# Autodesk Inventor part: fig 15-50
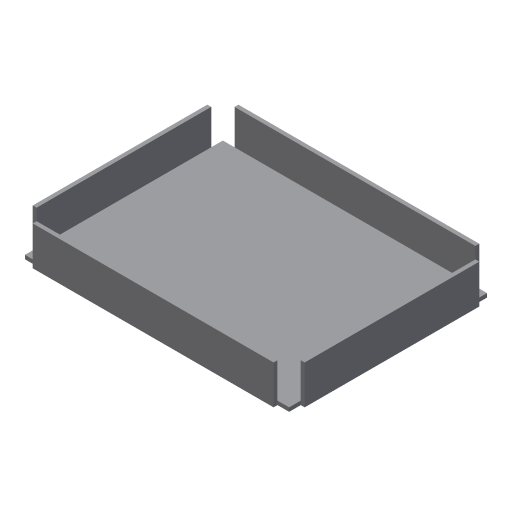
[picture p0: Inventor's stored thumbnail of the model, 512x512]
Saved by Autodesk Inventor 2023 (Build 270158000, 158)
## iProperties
Created: 2002-04
Part Number: fig 15-50
Document SubType Name: Sheet Metal
Density: 1 g/cm^3
Sheet Metal Rule: Default
Material: Generic
Appearance: Default
Control State: 0
Master: False
Checked Out: False
Shininess: 77.0
Angle Display Precision: 2
Document Length Units: 11269
Document Angle Units: 11279
Document Time Units: 11290
Document Mass Units: 11283
Document Length Units Precision: 3
Document Angle Units Precision: 2
Compacted: True
Density: 0.0
Volumn: 0.0
Area: 0.0
PropertySet Name: Model Information
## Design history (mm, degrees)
sketch "Sketch1"
  geometry: L1 (-34, 28)-(36, 28); L2 (36, 28)-(36, -24.941); L3 (36, -24.941)-(-34, -24.941); L4 (-34, -24.941)-(-34, 28)
  constraints: 8 end point, 2 parallel, 1 horizontal, 1 perpendicular
extrude "Extrusion1" join sketch "Sketch1" distance "d0" = 10; taper "d1" = 0 deg
shell "Shell1" dims "d2" = 1
feature "Corner9" dims "d27" = 4 (= CornerReliefSize), "d28" = 1 (= BendRadius), "d29" = 3, "d30" = 0, "d31" = 10, "d37" = 1 (= Thickness)
feature "Corner10" dims "d32" = 4 (= CornerReliefSize), "d33" = 1 (= BendRadius), "d34" = 3, "d35" = 0, "d36" = 10, "d37" = 1 (= Thickness)
body "Solid1"
other parameters: "Thickness" = 1, "BendRadius" = 1 (= Thickness), "BendReliefWidth" = 1 (= Thickness), "BendReliefDepth" = 0.5 (= 0.5 x Thickness), "CornerReliefSize" = 4 (= 4 x Thickness), "SeamGap" = 0.01, "MinimumRemnant" = 2 (= 2 x Thickness), "TransitionRadius" = 1 (= BendRadius), "JacobiRadiusSize" = 1 (= Thickness), "GapSize" = 1 (= Thickness)
